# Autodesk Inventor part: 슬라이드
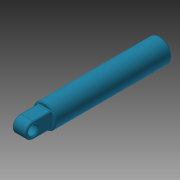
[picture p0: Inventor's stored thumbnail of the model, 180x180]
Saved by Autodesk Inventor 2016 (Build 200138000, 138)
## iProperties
Created: 2016-02
Part Number: 슬라이드
Material: 강철, 연강
Document SubType Name: Modeling
Designer: test
Density: 1 g/cm^3
Appearance: 회색
Author: test
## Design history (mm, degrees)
sketch "스케치2"
  geometry: C1 r 6 at (0, 0); 1 further point
  constraints: 1 centre point, 1 coincident
  dimensions: "d0" = 12 diameter of C1
extrude "돌출1" new body sketch "스케치2" distance "d1" = 60; taper "d2" = 0 deg
hole "구멍1" diameter "d5" = 5.917; stored, may be unused: countersink angle "d9" = 90 deg, drill point angle "d11" = 118 deg; dims "d3" = 10, "d4" = 10, "d6" = 10, "d7" = 4, "d8" = 2, "d10" = 12
chamfer "모따기1" distance "d12" = 1; stored, may be unused: second distance "d13" = 2, angle "d14" = 45 deg
sketch "스케치3"
  geometry: L1 (0, 6)-(0, -6) reference; L2 (0, 4)-(-9, 4); L3 (-9, -4)-(0, -4); L4 (0, -4)-(0, 4); C1 r 2.5 at (-9, 0); A1 r 4 centre (-9, 0) between (-9, 4) and (-9, -4); 2 further points
  constraints: 6 end point, 2 centre point, 2 point on circle, 2 tangent, 1 coincident, 1 horizontal, 1 horizontal alignment, 1 midpoint, 1 parallel, 1 point on line, 1 vertical
  dimensions: "d15" = 13 dimension on A1 L1; "d16" = 8 distance between parallel lines of L3 L2; "d17" = 5 diameter of C1
extrude "돌출2" join sketch "스케치3" stored distance "d18" = 7; taper "d19" = 0 deg
chamfer "모따기2" distance "d20" = 0.5; stored, may be unused: second distance "d21" = 2, angle "d22" = 45 deg
fillet "모깎기1" dims "d23" = 0.5
fillet "모깎기2" dims "d24" = 0.5
fillet "모깎기3" dims "d25" = 0.5
node "솔리드1"
